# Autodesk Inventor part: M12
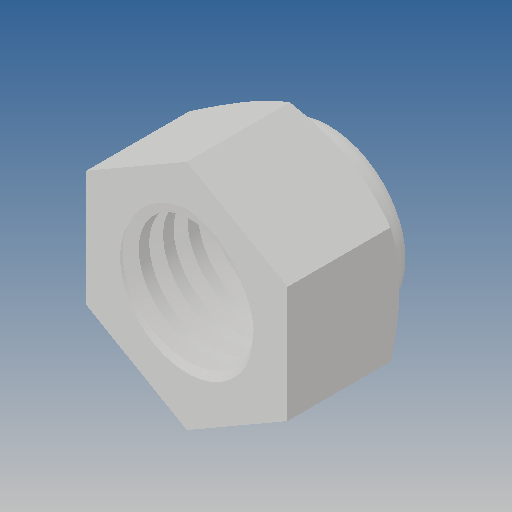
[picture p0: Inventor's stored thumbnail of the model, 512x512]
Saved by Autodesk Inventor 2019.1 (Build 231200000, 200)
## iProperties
Created: 2012-10
Part Number: M12
Material: Ogólny
Document SubType Name: Modeling
Designer: CADENGINEERING4
Density: 1 g/cm^3
Appearance: Domyślna
Author: CADENGINEERING4
Revision Number: ÈÎºÎ
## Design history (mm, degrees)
feature "ÊäÈë1"
node "Bryła1"
